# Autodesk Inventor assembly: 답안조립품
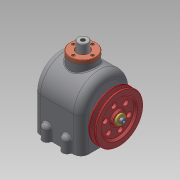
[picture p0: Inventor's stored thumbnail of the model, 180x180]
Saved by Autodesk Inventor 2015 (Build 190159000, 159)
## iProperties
Created: 2023-03
Part Number: 답안조립품
Document SubType Name: Assembly
Designer: home
Author: home
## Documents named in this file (22)
- C:\Users\home\Desktop\730306V1008\답안조립품.iam
- C:\Users\home\Desktop\730306V1008\E형 멈춤링 13 x 12.ipt
- C:\Users\home\Desktop\730306V1008\V-벨트풀리.ipt
- C:\Users\home\Desktop\730306V1008\고정핀.ipt
- C:\Users\home\Desktop\730306V1008\뒷커버.ipt
- C:\Users\home\Desktop\730306V1008\링크.ipt
- C:\Users\home\Desktop\730306V1008\멈춤링 25 x 1.2.ipt
- 멈춤링 25 x 1.2.ipt
- C:\Users\home\Desktop\730306V1008\베어링 6205.ipt
- 베어링 6205.ipt
- C:\Users\home\Desktop\730306V1008\본체.ipt
- C:\Users\home\Desktop\730306V1008\볼트 M4 x 12.ipt
- C:\Users\home\Desktop\730306V1008\볼트 M8 x 16.ipt
- C:\Users\home\Desktop\730306V1008\부시.ipt
- C:\Users\home\Desktop\730306V1008\슬라이더.ipt
- C:\Users\home\Desktop\730306V1008\앞커버.ipt
- C:\Users\home\Desktop\730306V1008\엔드캡.ipt
- C:\Users\home\Desktop\730306V1008\오일실 25 40 8.ipt
- 오일실 25 40 8.ipt
- C:\Users\home\Desktop\730306V1008\윗커버.ipt
- C:\Users\home\Desktop\730306V1008\키 6x6x14.ipt
- C:\Users\home\Desktop\730306V1008\편심축.ipt
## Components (3 placed, 3 different names)
1. E형 멈춤링 13 x 12:1
2. V-벨트풀리:1
3. 고정핀:1
